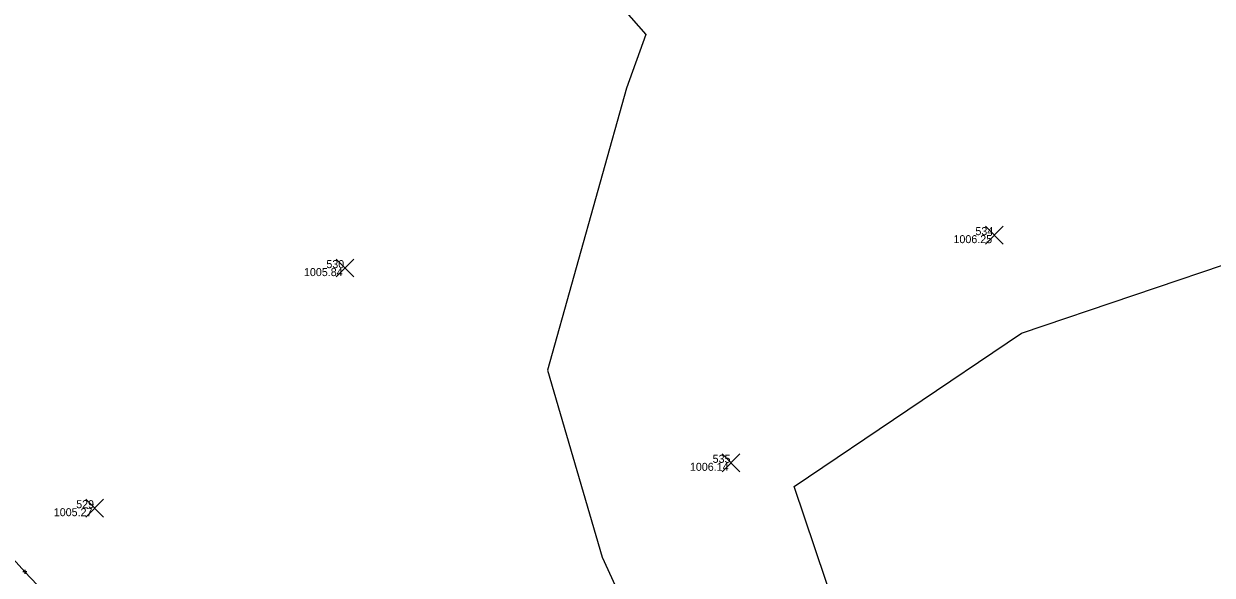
# Model space of a CAD drawing. Extents: x 2354693 to 2355622, y 637071 to 710080.
# Drawn here: x 2355257.5 to 2355435.7, y 709490.9 to 709573.6 of the extents above; entities that cross this region are included whole.
import ezdxf

# ---------------------------------------------------------------- set-up
doc = ezdxf.new("R2010")
doc.units = 0
for name, color, linetype in [('DT_X_Contour_Minor', 7, 'Continuous'), ('SV_X_Random_Point', 7, 'Continuous'), ('SV_X_Shot_Marker', 7, 'Continuous'), ('SV_X_Text_Elevation', 7, 'Continuous'), ('SV_X_Text_Name', 7, 'Continuous'), ('SV_X_Toe_of_Slope', 7, 'Continuous')]:
    doc.layers.add(name, color=color, linetype=linetype)

msp = doc.modelspace()

# ---------------------------------------------------------------- linework, layer by layer
at = {"layer": 'DT_X_Contour_Minor'}
for points in [[(2355346.36, 709576.98), (2355350.77, 709572.01), (2355347.88, 709563.96), (2355336.01, 709521.67), (2355344.22, 709493.66), (2355357.75, 709464.2)], [(2355346.36, 709576.98), (2355350.77, 709572.01), (2355347.88, 709563.96), (2355336.01, 709521.67), (2355344.22, 709493.66), (2355357.75, 709464.2)], [(2355388.83, 709457.34), (2355373.05, 709504.25), (2355407.1, 709527.21), (2355440.82, 709538.59)], [(2355388.83, 709457.34), (2355373.05, 709504.25), (2355407.1, 709527.21), (2355440.82, 709538.59)]]:
    msp.add_lwpolyline(points, dxfattribs=at)
at = {"layer": 'SV_X_Random_Point'}
for p, q in [((2355401.7, 709540.58), (2355404.36, 709543.25)), ((2355401.7, 709543.25), (2355404.36, 709540.58)), ((2355304.34, 709535.64), (2355307.01, 709538.31)), ((2355304.34, 709538.31), (2355307.01, 709535.64)), ((2355362.22, 709506.44), (2355364.89, 709509.11)), ((2355362.22, 709509.11), (2355364.89, 709506.44)), ((2355266.8, 709499.65), (2355269.46, 709502.32)), ((2355266.8, 709502.32), (2355269.46, 709499.65))]:
    msp.add_line(p, q, dxfattribs=at)
at = {"layer": 'SV_X_Shot_Marker'}
for p, q in [((2355257.66, 709491.73), (2355257.66, 709491.13)), ((2355257.96, 709491.43), (2355257.36, 709491.43))]:
    msp.add_line(p, q, dxfattribs=at)
at = {"layer": 'SV_X_Toe_of_Slope'}
msp.add_lwpolyline([(2355187.56, 709568.55), (2355223.43, 709529.36), (2355257.66, 709491.43), (2355294.21, 709452.95), (2355332.81, 709410.94), (2355352.9, 709375.39), (2355357.05, 709369.03), (2355359.18, 709363.17)], dxfattribs=at)

# ---------------------------------------------------------------- texts
at = {"layer": 'SV_X_Text_Elevation'}
for s, p in [('1006.25', (2355396.92, 709540.71)), ('1005.84', (2355299.51, 709535.77)), ('1006.14', (2355357.39, 709506.58)), ('1005.27', (2355261.99, 709499.78))]:
    msp.add_text(s, height=1.2, dxfattribs=at).set_placement(p)
at = {"layer": 'SV_X_Text_Name'}
for s, p in [('534', (2355400.21, 709541.91)), ('530', (2355302.87, 709536.97)), ('535', (2355360.8, 709507.78)), ('529', (2355265.35, 709500.98))]:
    msp.add_text(s, height=1.2, dxfattribs=at).set_placement(p)

doc.saveas('drawing.dxf')
